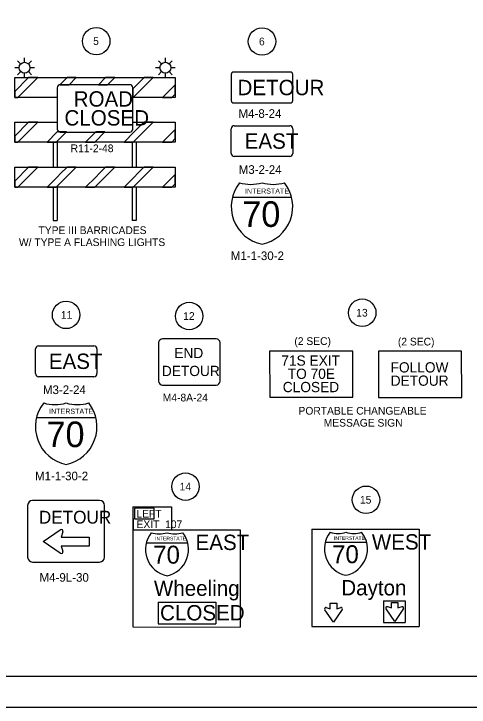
# Model space of a CAD drawing. Extents: x 0 to 680, y 0 to 440.
# Drawn here: x 439 to 587, y 0 to 225.4 of the extents above; entities that cross this region are included whole.
import ezdxf

# ---------------------------------------------------------------- set-up
doc = ezdxf.new("R2010")
doc.units = 0
for name, color, linetype in [('Default', 7, 'Continuous'), ('GM_X_County', 7, 'Continuous'), ('GM_X_Minor_Lake', 7, 'Continuous'), ('GM_X_Minor_River_Text', 7, 'Continuous'), ('GM_X_State_Shield', 7, 'Continuous'), ('GM_X_Unincorporated_Text', 7, 'Continuous'), ('GM_X_US_Shield', 7, 'Continuous')]:
    doc.layers.add(name, color=color, linetype=linetype)

msp = doc.modelspace()

# ---------------------------------------------------------------- linework, layer by layer
at = {"layer": 'Default'}
for p, q in [((439.27, 204.72), (491.43, 204.72)), ((439.27, 198.22), (439.27, 204.72)), ((491.43, 204.72), (491.43, 198.22)), ((453.07, 198.22), (439.27, 198.22)), ((491.43, 198.22), (477.66, 198.22)), ((439.27, 183.72), (439.27, 190.22)), ((439.27, 190.22), (453.07, 190.22)), ((477.66, 190.22), (491.43, 190.22)), ((491.43, 190.22), (491.43, 183.72)), ((491.43, 183.72), (439.27, 183.72)), ((451.77, 183.72), (451.77, 175.55)), ((453.1, 183.72), (453.1, 175.55)), ((477.43, 183.72), (477.43, 175.55)), ((478.77, 183.72), (478.77, 175.55)), ((439.27, 169.05), (439.27, 175.55)), ((439.27, 175.55), (477.66, 175.55)), ((477.66, 175.55), (491.43, 175.55)), ((491.43, 175.55), (491.43, 169.05)), ((491.43, 169.05), (439.27, 169.05)), ((451.77, 169.05), (451.77, 158.22)), ((453.1, 169.05), (453.1, 158.22)), ((477.43, 169.05), (477.43, 158.22)), ((478.77, 169.05), (478.77, 158.22)), ((451.77, 158.22), (453.1, 158.22)), ((478.77, 158.22), (477.43, 158.22))]:
    msp.add_line(p, q, dxfattribs=at)
at = {"layer": 'GM_X_County'}
msp.add_lwpolyline([(0, 0), (680, 0), (680, 440), (0, 440)], close=True, dxfattribs=at)
at = {"layer": 'GM_X_Minor_Lake'}
for p, q in [((441.2, 209.15), (440.2, 210.16)), ((442.46, 209.68), (442.46, 211.11)), ((444.73, 210.16), (443.72, 209.15)), ((486.98, 209.15), (485.97, 210.16)), ((488.24, 209.68), (488.24, 211.11)), ((490.5, 210.16), (489.5, 209.15)), ((440.7, 207.92), (439.27, 207.92)), ((445.66, 207.92), (444.23, 207.92)), ((486.47, 207.92), (485.04, 207.92)), ((491.43, 207.92), (490, 207.92)), ((441.22, 206.66), (440.21, 205.65)), ((442.46, 204.72), (442.46, 206.15)), ((444.71, 205.65), (443.71, 206.66)), ((486.99, 206.66), (485.99, 205.65)), ((488.24, 204.72), (488.24, 206.15)), ((490.49, 205.65), (489.48, 206.66))]:
    msp.add_line(p, q, dxfattribs=at)
for centre, radius in [((465.78, 216.57), 4.46), ((519.66, 216.46), 4.46), ((442.46, 207.92), 1.76), ((488.24, 207.92), 1.76), ((455.97, 127.54), 4.46), ((495.98, 127.18), 4.46), ((552.24, 128.26), 4.46), ((494.79, 71.7), 4.46), ((553.47, 67.43), 4.46)]:
    msp.add_circle(centre, radius, dxfattribs=at)
at = {"layer": 'GM_X_Minor_River_Text'}
msp.add_lwpolyline([(30, 430), (670, 430), (670, 10), (30, 10)], close=True, dxfattribs=at)
at = {"layer": 'GM_X_Unincorporated_Text'}
for p, q in [((443.8, 204.72), (439.27, 200.19)), ((440.3, 198.22), (446.8, 204.72)), ((446.8, 204.72), (443.8, 204.72)), ((456.3, 204.72), (453.97, 202.39)), ((459.3, 204.72), (456.3, 204.72)), ((456.97, 202.39), (459.3, 204.72)), ((468.8, 204.72), (466.47, 202.39)), ((471.8, 204.72), (468.8, 204.72)), ((469.47, 202.39), (471.8, 204.72)), ((477.66, 198.08), (484.3, 204.72)), ((481.3, 204.72), (477.66, 201.09)), ((484.3, 204.72), (481.3, 204.72)), ((453.97, 202.39), (456.97, 202.39)), ((466.47, 202.39), (469.47, 202.39)), ((477.66, 201.09), (477.66, 198.08)), ((491.43, 202.36), (487.3, 198.22)), ((491.43, 199.36), (491.43, 202.36)), ((439.27, 200.19), (439.27, 198.22)), ((490.3, 198.22), (491.43, 199.36)), ((439.27, 198.22), (440.3, 198.22)), ((487.3, 198.22), (490.3, 198.22)), ((443.8, 190.22), (439.27, 185.69)), ((440.3, 183.72), (446.8, 190.22)), ((446.8, 190.22), (443.8, 190.22)), ((477.8, 183.72), (484.3, 190.22)), ((481.18, 190.11), (479.29, 188.25)), ((481.3, 190.22), (481.18, 190.11)), ((484.3, 190.22), (481.3, 190.22)), ((479.29, 188.25), (478.11, 187.03)), ((491.43, 187.86), (487.3, 183.72)), ((491.43, 184.86), (491.43, 187.86)), ((509.66, 180.07), (509.66, 188.07)), ((510.66, 189.07), (528.66, 189.07)), ((529.66, 188.07), (529.66, 180.07)), ((439.27, 185.69), (439.27, 183.72)), ((453.11, 187.03), (449.8, 183.72)), ((452.8, 183.72), (456.11, 187.03)), ((456.11, 187.03), (453.11, 187.03)), ((465.61, 187.03), (462.3, 183.72)), ((465.3, 183.72), (468.61, 187.03)), ((468.61, 187.03), (465.61, 187.03)), ((478.11, 187.03), (474.8, 183.72)), ((439.27, 183.72), (440.3, 183.72)), ((462.3, 183.72), (465.3, 183.72)), ((487.3, 183.72), (490.3, 183.72)), ((490.3, 183.72), (491.43, 184.86)), ((528.66, 179.07), (510.66, 179.07)), ((443.8, 175.55), (439.27, 171.02)), ((440.3, 169.05), (446.8, 175.55)), ((446.8, 175.55), (443.8, 175.55)), ((452.8, 169.05), (459.3, 175.55)), ((456.18, 175.44), (454.29, 173.59)), ((456.3, 175.55), (456.18, 175.44)), ((459.3, 175.55), (456.3, 175.55)), ((465.3, 169.05), (471.8, 175.55)), ((468.68, 175.44), (466.79, 173.59)), ((468.8, 175.55), (468.68, 175.44)), ((471.8, 175.55), (468.8, 175.55)), ((477.8, 169.05), (484.3, 175.55)), ((481.18, 175.44), (479.29, 173.59)), ((481.3, 175.55), (481.18, 175.44)), ((484.3, 175.55), (481.3, 175.55)), ((453.11, 172.37), (449.8, 169.05)), ((454.29, 173.58), (453.11, 172.37)), ((465.61, 172.37), (462.3, 169.05)), ((466.79, 173.58), (465.61, 172.37)), ((478.11, 172.37), (474.8, 169.05)), ((479.29, 173.58), (478.11, 172.37)), ((491.43, 173.19), (487.3, 169.05)), ((491.43, 170.19), (491.43, 173.19)), ((439.27, 171.02), (439.27, 169.05)), ((490.3, 169.05), (491.43, 170.19)), ((439.27, 169.05), (440.3, 169.05)), ((487.3, 169.05), (490.3, 169.05)), ((447.01, 117.46), (465.01, 117.46)), ((446.01, 108.46), (446.01, 116.46)), ((466.01, 116.46), (466.01, 108.46)), ((465.01, 107.46), (447.01, 107.46)), ((448.47, 53.84), (454.09, 57.66)), ((454.95, 57.01), (454.41, 55.31)), ((454.41, 55.31), (463.47, 55.31)), ((463.47, 55.31), (463.47, 52.39)), ((454.09, 50.04), (448.47, 53.84)), ((463.47, 52.39), (454.41, 52.39)), ((454.41, 52.39), (454.95, 50.69)), ((542.91, 27.59), (540.12, 31.67)), ((540.54, 32.36), (541.82, 31.96)), ((541.82, 31.96), (541.82, 33.76)), ((541.82, 33.76), (543.95, 33.76)), ((545.76, 31.73), (542.91, 27.59)), ((543.95, 33.76), (543.95, 31.94)), ((543.95, 31.94), (545.29, 32.36)), ((545.76, 31.73), (545.76, 31.73))]:
    msp.add_line(p, q, dxfattribs=at)
for points in [[(509.66, 205.69), (509.66, 197.29)], [(528.86, 206.49), (510.46, 206.49)], [(529.66, 197.29), (529.66, 205.69)], [(453.07, 201.42), (453.07, 187.98)], [(476.7, 202.39), (454.03, 202.39)], [(477.66, 187.98), (477.66, 201.42)], [(510.46, 196.49), (528.86, 196.49)], [(454.03, 187.01), (476.7, 187.01)], [(449.8, 183.72), (451.77, 183.72), (452.8, 183.72)], [(474.8, 183.72), (477.43, 183.72), (477.8, 183.72)], [(449.8, 169.05), (452.43, 169.05), (452.8, 169.05)], [(462.3, 169.05), (464.93, 169.05), (465.3, 169.05)], [(474.8, 169.05), (477.43, 169.05), (477.8, 169.05)], [(504.74, 119.75), (487.34, 119.75)], [(486.04, 118.45), (486.04, 106.05)], [(506.04, 106.05), (506.04, 118.45)], [(549.13, 115.8), (522.13, 115.8)], [(522.13, 115.8), (522.18, 100.74)], [(549.18, 100.74), (549.13, 115.8)], [(584.54, 115.73), (557.53, 115.73)], [(557.53, 115.73), (557.58, 100.67)], [(584.58, 100.67), (584.54, 115.73)], [(487.34, 104.75), (504.74, 104.75)], [(522.18, 100.74), (549.18, 100.74)], [(557.58, 100.67), (584.58, 100.67)], [(443.47, 65.58), (443.47, 48.78)], [(466.87, 67.18), (445.07, 67.18)], [(468.47, 48.78), (468.47, 65.58)], [(445.07, 47.18), (466.87, 47.18)]]:
    msp.add_lwpolyline(points, dxfattribs=at)
for centre, radius, start, end in [((510.46, 205.69), 0.8, 90, 180), ((528.86, 205.69), 0.8, 360, 90), ((454.03, 201.42), 0.963, 90, 180), ((476.7, 201.42), 0.963, 0, 90), ((510.46, 197.29), 0.8, 180, 270), ((528.86, 197.29), 0.8, 270, 360), ((454.03, 187.98), 0.963, 180, 270), ((476.7, 187.98), 0.963, 270, 0), ((479.29, 188.25), 0.00405, 270, 0), ((510.66, 188.07), 1, 90, 180), ((528.66, 188.07), 1, 360, 90), ((510.66, 180.07), 1, 180, 270), ((528.66, 180.07), 1, 270, 360), ((454.29, 173.59), 0.00405, 270, 0), ((466.79, 173.59), 0.00405, 270, 0), ((479.29, 173.59), 0.00405, 270, 0), ((487.34, 118.45), 1.3, 90, 180), ((504.74, 118.45), 1.3, 0, 90), ((447.01, 116.46), 1, 90, 180), ((465.01, 116.46), 1, 360, 90), ((447.01, 108.46), 1, 180, 270), ((465.01, 108.46), 1, 270, 360), ((487.34, 106.05), 1.3, 180, 270), ((504.74, 106.05), 1.3, 270, 0), ((445.07, 65.58), 1.6, 90, 180), ((466.87, 65.58), 1.6, 360, 90), ((454.41, 57.18), 0.572, 342.1992, 124.1969), ((454.41, 50.51), 0.572, 235.8031, 17.8008), ((445.07, 48.78), 1.6, 180, 270), ((466.87, 48.78), 1.6, 270, 360), ((540.41, 31.96), 0.417, 72.7954, 225.0849), ((545.41, 31.96), 0.417, 325.4112, 107.2046)]:
    msp.add_arc(centre, radius, start, end, dxfattribs=at)
at = {"layer": 'GM_X_US_Shield'}
for p, q in [((510.04, 165.84), (529.28, 165.84)), ((446.39, 94.23), (465.63, 94.23)), ((477.72, 65.09), (477.72, 26.06)), ((512.56, 57.7), (512.56, 26.05)), ((535.9, 57.85), (535.88, 26.21)), ((570.72, 57.85), (570.72, 26.2)), ((482.06, 53.44), (495.52, 53.44)), ((540.21, 53.59), (553.68, 53.59)), ((485.95, 34.08), (504.6, 34.08)), ((485.95, 34.08), (485.95, 27.04)), ((504.6, 34.08), (504.6, 27.04)), ((559.19, 34.58), (559.19, 27.53)), ((559.19, 34.58), (566.23, 34.57)), ((566.23, 34.57), (566.23, 27.53)), ((559.19, 27.53), (566.23, 27.53)), ((485.95, 27.04), (504.6, 27.04))]:
    msp.add_line(p, q, dxfattribs=at)
for points in [[(477.72, 65.09), (477.74, 57.7)], [(477.72, 65.09), (490.19, 65.09)], [(478.18, 64.72), (478.19, 61.18), (484.65, 61.18), (484.65, 64.68), (478.18, 64.71)], [(490.19, 65.09), (490.21, 57.7)], [(477.74, 57.7), (512.56, 57.7)], [(535.9, 57.85), (570.72, 57.85)], [(560.41, 32.67), (560.41, 32.67), (561.7, 32.27), (561.7, 34.06), (563.83, 34.06), (563.83, 32.25), (565.17, 32.67), (565.17, 32.67)], [(565.63, 32.03), (565.63, 32.03), (562.79, 27.89), (560, 31.97)], [(477.72, 26.06), (512.56, 26.05)], [(535.88, 26.21), (570.72, 26.2)]]:
    msp.add_lwpolyline(points, dxfattribs=at)
for centre, radius, start, end in [((522.16, 162.77), 12.5, 141.669, 258.463), ((516.01, 182.48), 12.5, 253.0091, 286.9909), ((523.31, 182.48), 12.5, 253.0091, 286.9909), ((517.16, 162.77), 12.5, 281.537, 38.331), ((458.51, 91.17), 12.5, 141.669, 258.463), ((452.36, 110.87), 12.5, 253.0091, 286.9909), ((459.66, 110.87), 12.5, 253.0091, 286.9909), ((453.51, 91.17), 12.5, 281.537, 38.331), ((490.54, 51.29), 8.75, 141.669, 258.463), ((486.23, 65.09), 8.75, 253.0091, 286.9909), ((491.35, 65.09), 8.75, 253.0091, 286.9909), ((487.04, 51.29), 8.75, 281.537, 38.331), ((548.69, 51.45), 8.75, 141.669, 258.463), ((544.39, 65.24), 8.75, 253.0091, 286.9909), ((549.5, 65.24), 8.75, 253.0091, 286.9909), ((545.19, 51.45), 8.75, 281.537, 38.331), ((560.29, 32.27), 0.417, 72.7954, 225.0849), ((565.29, 32.27), 0.417, 325.4112, 107.2046)]:
    msp.add_arc(centre, radius, start, end, dxfattribs=at)

# ---------------------------------------------------------------- texts
at = {"layer": 'Default'}
for s, p in [('TYPE III BARRICADES ', (447.01, 153.83)), ('W/ TYPE A FLASHING LIGHTS', (440.64, 149.93))]:
    msp.add_text(s, height=2.5, dxfattribs=at).set_placement(p)
at = {"layer": 'GM_X_Minor_Lake'}
for s, p in [('5', (464.78, 215.32)), ('6', (518.67, 215.21)), ('11', (454.29, 126.29)), ('13', (550.29, 127.01)), ('12', (494.03, 125.93)), ('14', (492.87, 70.45)), ('15', (551.5, 66.18))]:
    msp.add_text(s, height=2.5, dxfattribs=at).set_placement(p)
at = {"layer": 'GM_X_State_Shield'}
for s, height, p in [('M4-8-24', 2.8, (512.03, 191.62)), ('R11-2-48', 2.5, (457.45, 180.46)), ('M3-2-24', 2.8, (512.09, 173.41)), ('M1-1-30-2', 2.8, (509.52, 145.37)), ('(2 SEC)', 2.5, (530.18, 117.78)), ('(2 SEC)', 2.5, (563.83, 117.61)), ('M3-2-24', 2.8, (448.45, 101.8)), ('M4-8A-24', 2.5, (487.4, 99.41)), ('PORTABLE CHANGEABLE', 2.5, (531.52, 95.12)), ('MESSAGE SIGN', 2.5, (539.73, 91.22)), ('M1-1-30-2', 2.8, (445.87, 73.76)), ('M4-9L-30', 2.8, (447.34, 40.78))]:
    msp.add_text(s, height=height, dxfattribs=at).set_placement(p)
at = {"layer": 'GM_X_Unincorporated_Text'}
for s, height, p in [('DETOUR', 5, (511.69, 198.99)), ('ROAD', 5, (458.43, 195.27)), ('CLOSED', 5, (455.44, 189.12)), ('EAST', 5, (514.02, 181.57)), ('EAST', 5, (450.37, 109.96)), ('END', 3.333, (491.15, 113.48)), ('71S EXIT ', 3.333, (525.93, 111.04)), ('DETOUR', 3.333, (487.11, 107.66)), ('FOLLOW', 3.333, (561.45, 108.82)), ('TO 70E ', 3.333, (528.03, 106.73)), ('DETOUR', 3.333, (561.49, 104.5)), ('CLOSED', 3.333, (526.41, 102.42)), ('DETOUR', 4.167, (447.12, 59.68))]:
    msp.add_text(s, height=height, dxfattribs=at).set_placement(p)
at = {"layer": 'GM_X_US_Shield'}
for s, height, p in [('INTERSTATE', 1.667, (514.12, 166.98)), ('70', 8.333, (513.23, 156.15)), ('INTERSTATE', 1.667, (450.47, 95.38)), ('70', 8.333, (449.59, 84.54)), ('LEFT', 2.5, (478.82, 61.65)), ('EXIT  107', 2.5, (478.88, 58.22)), ('INTERSTATE', 1.167, (484.91, 54.24)), ('EAST', 5, (498.06, 51.08)), ('INTERSTATE', 1.167, (543.06, 54.4)), ('WEST', 5, (555.35, 51.24)), ('70', 5.833, (484.29, 46.66)), ('70', 5.833, (542.45, 46.81)), ('Wheeling', 5, (484.51, 36.17)), ('Dayton', 5, (545.43, 36.33)), ('CLOSED', 5, (486.52, 28.19))]:
    msp.add_text(s, height=height, dxfattribs=at).set_placement(p)

doc.saveas('drawing.dxf')
